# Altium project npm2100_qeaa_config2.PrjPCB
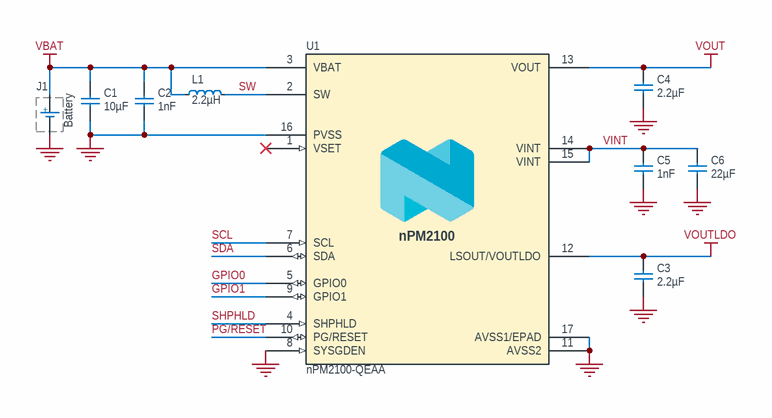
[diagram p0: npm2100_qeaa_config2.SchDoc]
1 sheet, 9 parts. Net scope: global (net labels, ports and power ports of the same name join across sheets).
Board file: npm2100_qeaa_config2.PcbDoc

## Sheet npm2100_qeaa_config2.SchDoc: nPM2100-QxAA Ref. Full Configuration
size A4; Revision: 0.2; SheetNumber: 1; SheetTotal: 1; DrawnBy: DABA; DocumentSize: A4; BoardTitle: nPM2100-QxAA Ref. Full Configuration; PCAName: nPM2100-QEAA; RefLayoutTitle: Reference Layout Config. 2: Full Configuration; Device: nPM2100-QEAA; Classification: Public

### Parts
C1  10µF  [CAPC1005X04L_C2]
C2  1nF  [CAPC0603X03L_C]
C3  2.2µF  [CAPC1005X04L_C2]
C4  2.2µF  [CAPC1005X04L_C2]
C5  1nF  [CAPC0603X03L_C]
C6  22µF  [CAPC1005X04L_C2]
J1  Battery  [TP_2x1mm_TH]  (graphical)
L1  2.2µH  [INDC2016X18N]
U1  nPM2100-QEAA  [QFN65P400X400X65_HS-17N]

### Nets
GND: C1.1 C2.1 C3.1 C4.1 C5.1 C6.1 J1.1(GND) U1.8(SYSGDEN) U1.11(AVSS2) U1.16(PVSS) U1.17(AVSS1/EPAD)
VBAT: C1.2 C2.2 J1.2(V+) L1.1 U1.3(VBAT)
VOUT: C4.2 U1.13(VOUT)
VOUTLDO: C3.2 U1.12(LSOUT/VOUTLDO)
GPIO0: U1.5(GPIO0)
GPIO1: U1.9(GPIO1)
PG/RESET: U1.10(PG/RESET)
SCL: U1.7(SCL)
SDA: U1.6(SDA)
SHPHLD: U1.4(SHPHLD)
SW: L1.2 U1.2(SW)
VINT: C5.2 C6.2 U1.14(VINT) U1.15(VINT)

Not connected (* = marked no-connect by the designer): U1 1(VSET)*

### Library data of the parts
C1 = C0402-10µ-6.3V-X5R-GRM155R60J106ME05D: Capacitor, X5R, ±20%, 6.3V; Manufacturer: Murata; Part number NEMS: 100200554; Component Status: Active; Pad Count: 2; Artikkelnr Noca: N.A.
C2 C5 = C0201-1n0-50V-X7R: Capacitor, X7R, ±10pF, 50V; Manufacturer: Murata; Manufacturer Part Number: GRM033R71H102KA12D; Part number NEMS: 100200404; Component Status: Active; Pad Count: 2; Artikkelnr Noca: N.A.
C3 C4 = C0402-2µ2-16V-X6S-GRM155C81C225KE11D: Capacitor, X6S, ±10%, 16V; Manufacturer: Murata; Part number NEMS: 100200556; Component Status: Active; Pad Count: 2; Artikkelnr Noca: N.A.
C6 = C0402-22µ-6.3V-X5R-GRM158R60J226ME01D: Capacitor, X5R, ±20%, 6.3V; Manufacturer: Murata; Part number NEMS: 100200555; Component Status: Active; Pad Count: 2; Artikkelnr Noca: N.A.
J1 = Battery_TP: Manufacturer: N.A.; Part number NEMS: 101800006; Component Status: Active; Pad Count: 3
L1 = L0806-2µ2-1.2A-137.5mOhm-MLP2016H2R2MT0S1: Shielded Multilayer Inductor, 1.2A, ±20%, 137.5mOhm; Manufacturer: TDK Corporation; Part number NEMS: 100300426; Component Status: Active; Pad Count: 2; Note: N.A.
U1 = nPM2100-QEAA: Boost converter companion PMIC for maximum energy extraction of primary (no-rechargeable) batteries; Manufacturer: Nordic Semiconductor; Part number NEMS: 102000298; Component Status: Active; Pad Count: 17; Note: N.A.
